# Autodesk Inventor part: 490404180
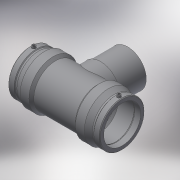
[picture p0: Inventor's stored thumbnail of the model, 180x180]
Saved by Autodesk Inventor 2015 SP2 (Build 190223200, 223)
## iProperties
Created: 2017-06
Part Number: 490404180
Material: Generic
Description: PLASSON TEE 180-180-180
Document SubType Name: Modeling
Designer: KIM
Mass: 8536.18 g
Surface Area: 7179.6 cm^2
Volume: 8536.18 cm^3
Density: 1 g/cm^3
Appearance: Default
Author: KIM
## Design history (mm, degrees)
derived "490404.ipt"
feature "Solid1::490404.ipt"
tag "TaggingFeature1"
body "Solid1"
other parameters: "d0" = 422, "d2" = 245, "d3" = 106, "d4" = 105.5, "d5" = 220.5, "d6" = 171, "d8" = 168 deg, "d10" = 42.4, "d11" = 14.13333, "d13" = 422, "d14" = 17.6296, "d17" = 162, "d19" = 3.52592, "d20" = 168 deg, "d22" = 227.85, "d23" = 245, "d24" = 221.0145, "d25" = 135 deg, "d26" = 295.4, "d27" = 135 deg, "d29" = 116, "d30" = 15, "d31" = 168.8, "d34" = 5 deg, "d35" = 15, "d39" = 5 deg, "d40" = 9.6, "d41" = 4.8, "d42" = 6, "d43" = 0, "d45" = 4, "d46" = 14, "d47" = 0, "d51" = 0, "d52" = 144, "d54" = 0, "d55" = 220.5, "d56" = 245, "d57" = 147.7, "d58" = 135 deg, "d59" = 106, "d60" = 106, "d61" = 135 deg, "d72" = 192.01, "d73" = 96.005, "d75" = 189, "d77" = 0, "d78" = 144, "d80" = 0, "d82" = 127.5, "d83" = 0, "d84" = 3, "d85" = 0, "d86" = 3, "d87" = 0, "d88" = 30.74, "d89" = 7.685, "d90" = 30.74, "L_" = 422, "L_1" = 106, "D_" = 245, "A_" = 116, "d_2" = 12
